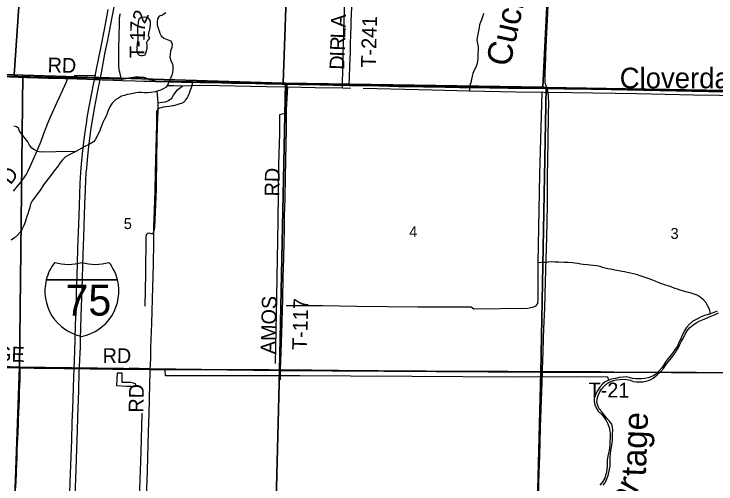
# Model space of a CAD drawing. Extents: x 1443599 to 1910620, y 1028088 to 1361369.
# Drawn here: x 1657763 to 1671995, y 1211112 to 1220636 of the extents above; entities that cross this region are included whole.
import ezdxf

# ---------------------------------------------------------------- set-up
doc = ezdxf.new("R2010")
doc.units = 0
for name, color, linetype in [('GM_X_County_Road', 7, 'Continuous'), ('GM_X_Interstate_Location', 7, 'Continuous'), ('GM_X_Interstate_Route', 7, 'Continuous'), ('GM_X_Interstate_Shield', 7, 'Continuous'), ('GM_X_Major_River', 7, 'Continuous'), ('GM_X_Major_River_Text', 7, 'Continuous'), ('GM_X_Minor_Lake', 7, 'Continuous'), ('GM_X_Minor_River', 7, 'Continuous'), ('GM_X_Minor_River_Text', 7, 'Continuous'), ('GM_X_Section', 7, 'Continuous'), ('GM_X_Section_Text', 7, 'Continuous'), ('GM_X_Township', 7, 'Continuous'), ('GM_X_Township_Road', 7, 'Continuous'), ('GM_X_Township_Road_Text', 7, 'Continuous'), ('GM_X_Unincorporated_Text', 7, 'Continuous')]:
    doc.layers.add(name, color=color, linetype=linetype)

msp = doc.modelspace()

# ---------------------------------------------------------------- linework, layer by layer
at = {"layer": 'GM_X_County_Road'}
for points in [[(1668570, 1219128), (1668552, 1219187), (1668542, 1219216), (1668535, 1219246), (1668530, 1219278), (1668530, 1219294), (1668529, 1219327), (1668531, 1219409), (1668541, 1219622), (1668545, 1219721), (1668549, 1219819), (1668569, 1220262), (1668574, 1220376), (1668588, 1220655), (1668603, 1221016), (1668610, 1221230), (1668626, 1221590), (1668635, 1221754), (1668637, 1221792)], [(1668476, 1213394), (1668478, 1213437), (1668490, 1213781), (1668500, 1214060), (1668507, 1214257), (1668525, 1214683), (1668540, 1215208), (1668547, 1215437), (1668555, 1215683), (1668567, 1216110), (1668574, 1216438), (1668578, 1216766), (1668582, 1217390), (1668585, 1217636), (1668599, 1218571), (1668604, 1218866), (1668603, 1218932), (1668600, 1218980), (1668591, 1219041), (1668577, 1219107), (1668570, 1219128)], [(1668309, 1208097), (1668308, 1208172), (1668312, 1208303), (1668320, 1208549), (1668326, 1208762), (1668336, 1209008), (1668344, 1209287), (1668363, 1209845), (1668392, 1210697), (1668401, 1210927), (1668405, 1211107), (1668412, 1211337), (1668423, 1211682), (1668440, 1212256), (1668469, 1213174), (1668476, 1213394)]]:
    msp.add_lwpolyline(points, dxfattribs=at)
at = {"layer": 'GM_X_Interstate_Route'}
for points in [[(1659004, 1210858), (1659022, 1211400), (1659036, 1211826), (1659047, 1212187), (1659057, 1212466), (1659075, 1213007), (1659087, 1213401), (1659089, 1213450), (1659091, 1213483), (1659100, 1213630), (1659107, 1213761), (1659111, 1213876), (1659114, 1214056), (1659117, 1214270), (1659124, 1214516), (1659143, 1215057), (1659166, 1215762), (1659179, 1216123), (1659201, 1216779), (1659210, 1217075), (1659219, 1217272), (1659228, 1217419), (1659236, 1217511), (1659251, 1217681), (1659273, 1217893), (1659301, 1218121), (1659335, 1218365), (1659366, 1218560), (1659400, 1218754), (1659461, 1219076), (1659508, 1219306), (1659535, 1219446), (1659614, 1219866), (1659662, 1220107), (1659727, 1220433), (1659756, 1220574), (1659833, 1220977)], [(1658897, 1210943), (1658910, 1211321), (1658932, 1212009), (1658942, 1212354), (1658953, 1212633), (1658975, 1213273), (1658981, 1213452), (1658993, 1213798), (1659009, 1214323), (1659021, 1214651), (1659032, 1214995), (1659044, 1215340), (1659051, 1215578), (1659060, 1215881), (1659073, 1216209), (1659083, 1216554), (1659097, 1216980), (1659107, 1217210), (1659120, 1217422), (1659134, 1217602), (1659160, 1217864), (1659181, 1218043), (1659213, 1218287), (1659237, 1218460), (1659240, 1218482), (1659262, 1218611), (1659323, 1218934), (1659397, 1219310), (1659430, 1219482), (1659534, 1220013), (1659628, 1220496), (1659674, 1220729)]]:
    msp.add_lwpolyline(points, dxfattribs=at)
at = {"layer": 'GM_X_Interstate_Shield'}
for p, q in [((1658417, 1215250), (1659860, 1215250)), ((1659860, 1215250), (1658417, 1215250)), ((1659860, 1215250), (1658417, 1215250))]:
    msp.add_line(p, q, dxfattribs=at)
for centre, start, end in [((1659326, 1215021), 141.669, 165.8066), ((1658865, 1216499), 253.0091, 286.9909), ((1659413, 1216499), 253.0091, 286.9909), ((1658951, 1215021), 14.1934, 38.331), ((1659326, 1215021), 165.8066, 258.463), ((1658951, 1215021), 281.537, 14.1934)]:
    msp.add_arc(centre, 938, start, end, dxfattribs=at)
at = {"layer": 'GM_X_Major_River'}
for points in [[(1660838, 1220661), (1660773, 1220610), (1660704, 1220593), (1660669, 1220538), (1660664, 1220482), (1660667, 1220420), (1660686, 1220351), (1660703, 1220297), (1660718, 1220246), (1660745, 1220196), (1660799, 1220145), (1660868, 1220117), (1660940, 1220090), (1660967, 1220027), (1660960, 1219957), (1660938, 1219885), (1660927, 1219819), (1660924, 1219763), (1660943, 1219697), (1660974, 1219622), (1660983, 1219570), (1660984, 1219505), (1660979, 1219453), (1660960, 1219399), (1660941, 1219348), (1660918, 1219292), (1660886, 1219220), (1660851, 1219153), (1660800, 1219124), (1660733, 1219091), (1660683, 1219078), (1660623, 1219061), (1660536, 1219046), (1660470, 1219037), (1660406, 1219040), (1660347, 1219045), (1660285, 1219044), (1660233, 1219037), (1660176, 1219024), (1660112, 1219012), (1660060, 1219002), (1660001, 1218987), (1659943, 1218968), (1659880, 1218933), (1659829, 1218904), (1659752, 1218831), (1659706, 1218754), (1659675, 1218678), (1659651, 1218619), (1659628, 1218567), (1659591, 1218493), (1659566, 1218436), (1659545, 1218384), (1659518, 1218316), (1659494, 1218256), (1659405, 1218084)], [(1659405, 1218084), (1659372, 1218044), (1659272, 1217985), (1659212, 1217959), (1659141, 1217919), (1659079, 1217885), (1659013, 1217849), (1658951, 1217819), (1658883, 1217784), (1658810, 1217742), (1658748, 1217682), (1658694, 1217612), (1658661, 1217562), (1658607, 1217495), (1658557, 1217431), (1658509, 1217363), (1658458, 1217299), (1658362, 1217171), (1658322, 1217107), (1658279, 1217047), (1658227, 1216981), (1658183, 1216917), (1658134, 1216849), (1658096, 1216779), (1658082, 1216715), (1658062, 1216653), (1658041, 1216584), (1658023, 1216530), (1658005, 1216468), (1657987, 1216418), (1657959, 1216348), (1657926, 1216284), (1657886, 1216216), (1657836, 1216154), (1657776, 1216098), (1657707, 1216050)], [(1672021, 1214612), (1671953, 1214584), (1671884, 1214563), (1671815, 1214540), (1671765, 1214527), (1671696, 1214498), (1671646, 1214469), (1671583, 1214441), (1671528, 1214411), (1671459, 1214350), (1671395, 1214285), (1671356, 1214217), (1671315, 1214144), (1671296, 1214092), (1671275, 1214038), (1671245, 1213977), (1671214, 1213907), (1671161, 1213834), (1671130, 1213782), (1671088, 1213731), (1671027, 1213656), (1670980, 1213594), (1670938, 1213527), (1670895, 1213463), (1670792, 1213347), (1670723, 1213304), (1670663, 1213275)], [(1670723, 1213256), (1670806, 1213321), (1670870, 1213386), (1670929, 1213453), (1670980, 1213524), (1671032, 1213593), (1671095, 1213668), (1671139, 1213732), (1671229, 1213867), (1671253, 1213923), (1671294, 1214004), (1671337, 1214073), (1671371, 1214145), (1671412, 1214214), (1671461, 1214274), (1671525, 1214329), (1671592, 1214376), (1671655, 1214410), (1671725, 1214439), (1671770, 1214461), (1671841, 1214491), (1671911, 1214518), (1671982, 1214547), (1672049, 1214580)], [(1670663, 1213275), (1670621, 1213263), (1670546, 1213247), (1670484, 1213244), (1670417, 1213241), (1670365, 1213244), (1670305, 1213251), (1670237, 1213267), (1670175, 1213280), (1670111, 1213279), (1670033, 1213266), (1669958, 1213250), (1669878, 1213233), (1669823, 1213218), (1669752, 1213179), (1669698, 1213131), (1669642, 1213075), (1669592, 1212998), (1669566, 1212949), (1669527, 1212846), (1669524, 1212782), (1669539, 1212712), (1669570, 1212643), (1669609, 1212590), (1669676, 1212525), (1669731, 1212462), (1669772, 1212397), (1669801, 1212330), (1669830, 1212259), (1669843, 1212195), (1669847, 1212127), (1669850, 1212054), (1669845, 1211980), (1669843, 1211906), (1669838, 1211850), (1669829, 1211792), (1669816, 1211734), (1669805, 1211678), (1669792, 1211604), (1669786, 1211520), (1669787, 1211468), (1669784, 1211416), (1669773, 1211344), (1669758, 1211288), (1669739, 1211232), (1669704, 1211163), (1669640, 1211087)], [(1669710, 1211090), (1669753, 1211150), (1669785, 1211213), (1669808, 1211283), (1669823, 1211343), (1669838, 1211409), (1669848, 1211475), (1669849, 1211539), (1669848, 1211607), (1669851, 1211657), (1669856, 1211721), (1669865, 1211789), (1669877, 1211867), (1669894, 1211941), (1669897, 1212005), (1669896, 1212081), (1669896, 1212130), (1669903, 1212196), (1669897, 1212260), (1669883, 1212324), (1669832, 1212392), (1669775, 1212453), (1669720, 1212520), (1669679, 1212571), (1669630, 1212636), (1669597, 1212699), (1669582, 1212767), (1669585, 1212831), (1669607, 1212907), (1669642, 1212979), (1669677, 1213030), (1669729, 1213093), (1669798, 1213154), (1669865, 1213191), (1669919, 1213210), (1669980, 1213221), (1670050, 1213232), (1670151, 1213235), (1670220, 1213221), (1670254, 1213212), (1670320, 1213191), (1670386, 1213180), (1670440, 1213179), (1670514, 1213181), (1670583, 1213196), (1670627, 1213211), (1670672, 1213231), (1670723, 1213256)]]:
    msp.add_lwpolyline(points, dxfattribs=at)
at = {"layer": 'GM_X_Minor_Lake'}
for p, q in [((1660268, 1220333), (1660272, 1220118)), ((1659954, 1213354), (1659852, 1213360))]:
    msp.add_line(p, q, dxfattribs=at)
for points in [[(1660272, 1220118), (1660257, 1220032), (1660256, 1219960), (1660254, 1219891), (1660269, 1219837), (1660301, 1219800), (1660335, 1219796), (1660365, 1219795), (1660423, 1219808), (1660451, 1219880), (1660460, 1219944), (1660463, 1219998), (1660458, 1220048), (1660464, 1220086), (1660487, 1220114), (1660514, 1220148), (1660493, 1220194), (1660499, 1220238), (1660523, 1220354), (1660531, 1220432), (1660528, 1220488), (1660503, 1220531), (1660463, 1220566), (1660399, 1220575), (1660327, 1220562), (1660294, 1220533), (1660279, 1220471), (1660274, 1220413), (1660268, 1220333)], [(1659852, 1213360), (1659841, 1213104), (1660047, 1213092), (1660138, 1213092), (1660176, 1213088), (1660206, 1213087), (1660234, 1213097), (1660231, 1213135), (1660183, 1213152), (1660131, 1213165), (1660095, 1213167), (1660043, 1213166), (1659956, 1213166), (1659954, 1213354)]]:
    msp.add_lwpolyline(points, dxfattribs=at)
at = {"layer": 'GM_X_Minor_River'}
for points in [[(1664420, 1219141), (1664430, 1219588), (1664467, 1220703), (1664502, 1221797)], [(1667283, 1220648), (1667261, 1220578), (1667240, 1220521), (1667221, 1220469), (1667204, 1220415), (1667191, 1220363), (1667178, 1220293), (1667165, 1220219), (1667152, 1220157), (1667149, 1220107), (1667161, 1220041), (1667174, 1219970), (1667175, 1219912), (1667166, 1219840), (1667169, 1219786), (1667170, 1219734), (1667163, 1219682), (1667144, 1219616), (1667125, 1219558), (1667095, 1219498), (1667066, 1219433), (1667053, 1219379), (1667038, 1219313), (1667027, 1219243), (1667000, 1219173), (1666996, 1219076)], [(1659424, 1219391), (1658982, 1219384)], [(1660681, 1218837), (1660771, 1218851), (1660832, 1218858), (1660896, 1218883), (1660963, 1218934), (1660997, 1218990), (1661031, 1219037), (1661087, 1219104), (1661136, 1219150), (1661177, 1219183)], [(1660870, 1219189), (1661006, 1219184), (1661177, 1219183), (1661532, 1219193), (1661917, 1219190), (1662884, 1219170), (1663307, 1219159), (1663869, 1219145), (1664420, 1219141), (1664587, 1219132)], [(1663307, 1219159), (1663281, 1218698), (1663272, 1218640), (1663239, 1218615), (1663191, 1218609), (1663146, 1218596), (1663146, 1218570), (1663146, 1218223), (1663124, 1217586), (1663110, 1216437), (1663086, 1214905), (1663055, 1213550)], [(1664842, 1219131), (1666248, 1219098), (1666996, 1219076), (1667940, 1219062), (1669064, 1219046), (1670392, 1219026), (1671541, 1219001), (1673126, 1218979), (1673804, 1218965), (1674957, 1218930), (1676782, 1218885), (1677987, 1218855), (1678918, 1218835), (1679686, 1218817), (1679915, 1218821), (1679981, 1218817), (1680013, 1218811), (1680035, 1218802), (1680071, 1218790), (1680088, 1218782), (1680162, 1218770), (1680189, 1218755), (1680204, 1218737), (1680229, 1218696)], [(1660657, 1219070), (1660672, 1218917), (1660681, 1218837), (1660678, 1218674), (1660662, 1218380), (1660651, 1217762), (1660643, 1217089), (1660609, 1216307), (1660600, 1216243), (1660577, 1216183), (1660545, 1216182), (1660503, 1216197), (1660467, 1216191), (1660446, 1216169), (1660437, 1216127), (1660432, 1215373), (1660416, 1214716)], [(1668462, 1219054), (1668418, 1217385), (1668381, 1215596), (1668384, 1214858), (1668376, 1214766), (1668333, 1214713), (1668277, 1214686), (1668176, 1214671), (1667086, 1214653), (1667031, 1214692), (1665951, 1214695), (1664714, 1214709), (1664012, 1214720), (1663281, 1214719)], [(1659013, 1217849), (1658614, 1217840), (1658304, 1217837), (1658240, 1217852), (1658176, 1217884), (1658124, 1217918), (1658080, 1217978), (1658042, 1218045), (1657876, 1218264), (1657854, 1218322), (1657816, 1218350), (1657758, 1218364)], [(1671884, 1214563), (1671862, 1214657), (1671821, 1214728), (1671794, 1214781), (1671741, 1214842), (1671673, 1214897), (1671612, 1214935), (1671550, 1214960), (1671492, 1214977), (1671414, 1214998), (1671336, 1215016), (1671269, 1215039), (1671217, 1215058), (1671163, 1215075), (1671087, 1215107), (1671023, 1215128), (1670970, 1215143), (1670900, 1215168), (1670824, 1215195), (1670764, 1215221), (1670693, 1215246), (1670641, 1215267), (1670583, 1215286), (1670519, 1215307), (1670459, 1215328), (1670386, 1215354), (1670324, 1215367), (1670260, 1215384), (1670194, 1215397), (1670138, 1215410), (1670084, 1215421), (1670028, 1215432), (1669948, 1215448), (1669858, 1215466), (1669806, 1215474), (1669752, 1215487), (1669698, 1215502), (1669646, 1215517), (1669580, 1215533), (1669506, 1215540), (1669442, 1215545), (1669388, 1215552), (1669306, 1215562), (1669254, 1215569), (1669186, 1215580), (1669136, 1215587), (1669086, 1215592), (1669001, 1215599), (1668919, 1215603), (1668801, 1215605), (1668733, 1215608), (1668663, 1215615), (1668596, 1215608), (1668542, 1215603), (1668460, 1215603), (1668381, 1215596)], [(1669823, 1213218), (1669805, 1213276), (1669173, 1213280), (1668000, 1213277), (1666861, 1213282), (1665834, 1213288), (1664588, 1213293), (1663567, 1213300), (1662885, 1213300), (1661889, 1213306), (1660835, 1213301), (1660826, 1213428), (1660509, 1213444), (1660100, 1213457)], [(1660232, 1208087), (1660232, 1208213), (1660242, 1208400), (1660260, 1209137), (1660290, 1210079), (1660309, 1210818), (1660343, 1211760), (1660364, 1212544)]]:
    msp.add_lwpolyline(points, dxfattribs=at)
at = {"layer": 'GM_X_Section'}
for points in [[(1652516, 1224828), (1658122, 1224661), (1657765, 1219401), (1652475, 1219581)], [(1658122, 1224661), (1663408, 1224572), (1663222, 1219236), (1657943, 1219395), (1657765, 1219401)], [(1663408, 1224572), (1668747, 1224447), (1668485, 1219152), (1663270, 1219233), (1663222, 1219236)], [(1674092, 1224359), (1673808, 1219056), (1668555, 1219147), (1668485, 1219152), (1668747, 1224447)], [(1652475, 1219581), (1657765, 1219401), (1657943, 1219395), (1657875, 1213479), (1652349, 1213674), (1652351, 1213940)], [(1657943, 1219395), (1663222, 1219236), (1663270, 1219233), (1663148, 1213408), (1657875, 1213479)], [(1668485, 1219152), (1668555, 1219147), (1668445, 1213380), (1663148, 1213408), (1663270, 1219233)], [(1668555, 1219147), (1673808, 1219056), (1673892, 1219051), (1673741, 1213362), (1668445, 1213380)], [(1652349, 1213674), (1657875, 1213479), (1657686, 1208189), (1652280, 1208398), (1652277, 1208611)], [(1657875, 1213479), (1663148, 1213408), (1663012, 1208124), (1657686, 1208189)], [(1668445, 1213380), (1668306, 1208094), (1663012, 1208124), (1663148, 1213408)], [(1673741, 1213362), (1673597, 1208030), (1668306, 1208094), (1668445, 1213380)]]:
    msp.add_lwpolyline(points, close=True, dxfattribs=at)
at = {"layer": 'GM_X_Township'}
for points in [[(1652299, 1208613), (1652365, 1213513), (1652367, 1213913), (1652370, 1214308), (1652390, 1216842), (1652463, 1219561), (1656589, 1219402), (1658837, 1219343), (1659402, 1219335), (1659951, 1219317), (1660040, 1219328), (1660129, 1219344), (1660227, 1219355), (1660302, 1219359), (1660400, 1219347), (1660510, 1219312), (1660641, 1219274), (1661382, 1219261), (1663295, 1219213), (1664558, 1219194), (1668556, 1219132), (1673810, 1219028)], [(1673810, 1219028), (1668556, 1219132), (1664558, 1219194), (1663295, 1219213), (1661382, 1219261), (1660641, 1219274), (1660510, 1219312), (1660400, 1219347), (1660302, 1219359), (1660227, 1219355), (1660129, 1219344), (1660040, 1219328), (1659951, 1219317), (1659402, 1219335), (1658837, 1219343), (1656589, 1219402)]]:
    msp.add_lwpolyline(points, dxfattribs=at)
at = {"layer": 'GM_X_Township_Road'}
for points in [[(1664601, 1220488), (1664606, 1220631), (1664614, 1220775), (1664621, 1220933), (1664634, 1221211), (1664640, 1221388), (1664651, 1221641), (1664658, 1221795), (1664660, 1221857), (1664661, 1221891)], [(1659951, 1219290), (1659944, 1219318), (1659907, 1219457), (1659902, 1219477), (1659898, 1219496), (1659894, 1219520), (1659892, 1219538), (1659890, 1219558), (1659888, 1219581), (1659886, 1219630), (1659887, 1219745), (1659889, 1219876), (1659897, 1220263), (1659900, 1220381), (1659900, 1220500), (1659902, 1220523), (1659903, 1220545), (1659905, 1220565), (1659907, 1220585), (1659910, 1220604), (1659914, 1220623), (1659919, 1220645)], [(1664558, 1219189), (1664558, 1219204), (1664559, 1219224), (1664562, 1219326), (1664572, 1219598), (1664576, 1219713), (1664582, 1219867), (1664585, 1219939), (1664588, 1220103), (1664589, 1220146), (1664589, 1220159), (1664590, 1220205), (1664593, 1220264), (1664596, 1220352), (1664601, 1220488)], [(1656645, 1219400), (1656663, 1219399), (1656991, 1219389), (1657237, 1219381), (1657368, 1219375), (1657466, 1219371), (1657598, 1219367), (1657680, 1219364), (1658024, 1219351), (1658451, 1219339), (1658506, 1219338)], [(1658506, 1219338), (1658615, 1219335), (1658795, 1219330), (1658849, 1219328)], [(1658639, 1218850), (1658685, 1218950), (1658788, 1219174), (1658821, 1219249), (1658831, 1219280), (1658849, 1219328)], [(1658849, 1219328), (1659041, 1219322), (1659238, 1219315), (1659397, 1219310), (1659508, 1219306), (1659549, 1219305), (1659583, 1219304), (1659779, 1219296), (1659951, 1219290)], [(1659951, 1219290), (1660222, 1219281), (1660386, 1219275), (1660534, 1219272), (1660632, 1219269)], [(1660526, 1213431), (1660526, 1213432), (1660531, 1213530), (1660535, 1213678), (1660539, 1213874), (1660555, 1214366), (1660578, 1215104), (1660585, 1215317), (1660592, 1215563), (1660601, 1216006), (1660600, 1216153), (1660601, 1216334), (1660611, 1216662), (1660623, 1217055), (1660632, 1217416), (1660639, 1217678), (1660658, 1218399), (1660659, 1218629), (1660661, 1218662), (1660664, 1218678), (1660669, 1218693), (1660678, 1218707), (1660690, 1218719), (1660704, 1218728), (1660718, 1218734), (1660750, 1218744), (1660797, 1218754), (1660847, 1218762), (1660911, 1218771), (1660946, 1218775), (1660976, 1218780), (1660996, 1218783), (1661024, 1218789), (1661072, 1218801), (1661135, 1218820), (1661165, 1218832), (1661195, 1218846), (1661209, 1218855), (1661222, 1218865), (1661232, 1218876), (1661243, 1218889), (1661271, 1218930), (1661295, 1218973), (1661309, 1219002), (1661321, 1219033), (1661336, 1219076), (1661359, 1219147), (1661372, 1219189), (1661376, 1219200), (1661377, 1219209), (1661379, 1219218), (1661380, 1219225), (1661382, 1219253)], [(1660632, 1219269), (1660928, 1219263), (1661157, 1219255), (1661321, 1219254), (1661382, 1219253)], [(1661382, 1219253), (1661535, 1219251), (1661797, 1219246), (1662159, 1219238), (1662437, 1219232), (1662667, 1219228), (1662848, 1219223), (1663012, 1219220), (1663192, 1219215), (1663302, 1219213)], [(1663167, 1213428), (1663171, 1213595), (1663184, 1213972), (1663198, 1214382), (1663204, 1214644), (1663210, 1214841), (1663222, 1215300), (1663228, 1215481), (1663233, 1215710), (1663241, 1216005), (1663245, 1216251), (1663250, 1216547), (1663259, 1216891), (1663267, 1217334), (1663279, 1218006), (1663286, 1218285), (1663290, 1218466), (1663290, 1218580), (1663286, 1218810), (1663290, 1218941), (1663297, 1219122), (1663301, 1219188), (1663302, 1219213)], [(1663302, 1219213), (1663389, 1219212), (1663537, 1219208), (1663767, 1219205), (1663964, 1219200), (1664243, 1219196), (1664456, 1219191), (1664558, 1219189)], [(1664558, 1219189), (1664784, 1219187), (1665162, 1219179), (1665556, 1219170), (1666065, 1219162), (1666508, 1219153), (1666803, 1219149), (1667050, 1219146), (1667411, 1219140), (1667788, 1219136), (1668100, 1219131), (1668570, 1219128)], [(1668570, 1219128), (1668921, 1219123), (1669150, 1219119), (1669462, 1219115), (1669889, 1219109), (1670168, 1219107), (1670628, 1219101), (1670858, 1219096), (1671071, 1219094), (1671334, 1219089), (1671760, 1219084), (1672335, 1219072), (1672565, 1219071), (1673336, 1219059), (1673550, 1219056), (1673664, 1219055), (1673802, 1219055)], [(1657752, 1217047), (1657925, 1217265), (1657974, 1217331), (1658001, 1217372), (1658027, 1217414), (1658049, 1217458), (1658090, 1217547), (1658170, 1217727), (1658230, 1217862), (1658276, 1217967), (1658312, 1218059), (1658366, 1218213), (1658412, 1218336), (1658449, 1218427), (1658508, 1218563), (1658639, 1218850)], [(1657599, 1213475), (1657845, 1213469), (1657890, 1213468)], [(1657801, 1211030), (1657809, 1211193), (1657813, 1211288), (1657815, 1211357), (1657820, 1211518), (1657825, 1211636), (1657826, 1211685), (1657830, 1211800), (1657836, 1211941), (1657845, 1212144), (1657851, 1212328), (1657854, 1212403), (1657860, 1212567), (1657864, 1212679), (1657871, 1212849), (1657872, 1212875), (1657874, 1212928), (1657877, 1213023), (1657878, 1213062), (1657885, 1213269), (1657888, 1213374), (1657889, 1213416), (1657890, 1213451), (1657890, 1213468)], [(1657890, 1213468), (1658038, 1213464)], [(1658038, 1213464), (1658174, 1213461), (1658338, 1213459), (1658617, 1213456), (1658781, 1213455), (1658981, 1213452), (1659089, 1213450), (1659306, 1213447), (1659552, 1213443), (1659765, 1213441), (1659962, 1213437), (1660045, 1213437)], [(1660045, 1213437), (1660126, 1213436), (1660274, 1213435), (1660526, 1213431)], [(1660360, 1208186), (1660360, 1208196), (1660360, 1208234), (1660360, 1208297), (1660365, 1208481), (1660378, 1208793), (1660394, 1209268), (1660411, 1209694), (1660421, 1210006), (1660430, 1210235), (1660435, 1210399), (1660449, 1210809), (1660468, 1211383), (1660490, 1212169), (1660501, 1212530), (1660508, 1212809), (1660515, 1213170), (1660521, 1213350), (1660526, 1213431)], [(1660526, 1213431), (1660536, 1213431), (1661111, 1213432), (1661357, 1213433), (1661702, 1213433), (1661997, 1213432), (1662309, 1213432), (1662670, 1213430), (1662933, 1213429), (1663167, 1213428)], [(1663166, 1213225), (1663167, 1213338), (1663167, 1213418), (1663167, 1213428)], [(1663167, 1213428), (1663245, 1213427), (1663803, 1213422), (1664147, 1213420), (1664344, 1213418), (1665149, 1213410), (1665543, 1213406), (1665822, 1213403), (1666117, 1213402), (1666494, 1213399), (1666675, 1213398), (1666839, 1213398), (1667019, 1213396), (1667282, 1213396), (1667577, 1213396), (1667774, 1213396), (1667939, 1213394), (1668431, 1213394), (1668476, 1213394)], [(1668476, 1213394), (1668529, 1213394), (1668759, 1213391), (1669137, 1213391), (1669662, 1213389), (1669925, 1213385), (1670171, 1213379), (1670532, 1213377), (1670679, 1213378), (1670844, 1213380), (1671041, 1213378), (1671270, 1213379), (1671599, 1213376), (1671779, 1213374), (1672370, 1213372), (1672600, 1213371), (1672830, 1213370), (1673174, 1213369), (1673388, 1213370), (1673716, 1213368), (1673782, 1213368)]]:
    msp.add_lwpolyline(points, dxfattribs=at)

# ---------------------------------------------------------------- texts
at = {"layer": 'GM_X_Interstate_Location'}
for s in ['.', '-', ',']:
    msp.add_text(s, height=1, dxfattribs=at).set_placement((1659139, 1214851))
msp.add_text('75', height=1, rotation=0, dxfattribs=at).set_placement((1658934, 1214644))
at = {"layer": 'GM_X_Interstate_Shield'}
msp.add_text('75', height=625, dxfattribs=at).set_placement((1658805, 1214524))
at = {"layer": 'GM_X_Major_River_Text'}
for s, height, rotation, p in [('tage', 500.2, 87.896, (1670572, 1211261)), ('or', 500.3, 60.895, (1670195, 1210574))]:
    msp.add_text(s, height=height, rotation=rotation, dxfattribs=at).set_placement(p)
at = {"layer": 'GM_X_Minor_River_Text'}
msp.add_text('Cuckle', height=500.3, rotation=77.4227, dxfattribs=at).set_placement((1667815, 1219549))
at = {"layer": 'GM_X_Section_Text'}
for s, p in [('5', (1659988, 1216278)), ('4', (1665776, 1216115)), ('3', (1671074, 1216078))]:
    msp.add_text(s, height=221, rotation=0, dxfattribs=at).set_placement(p)
at = {"layer": 'GM_X_Township_Road_Text'}
for s, rotation, p in [('2', 65.0293, (1660414, 1220422)), ('A', 88.0634, (1664486, 1220360)), ('T-241', 88.367, (1665096, 1219546)), ('7', 88.7607, (1660417, 1220269)), ('1', 88.7521, (1660413, 1220084)), ('L', 88.0583, (1664478, 1220136)), ('R', 88.0599, (1664470, 1219890)), ('T', 88.7485, (1660405, 1219736)), ('-', 88.7431, (1660410, 1219961)), ('I', 88.0641, (1664465, 1219767)), ('RD', 358.5255, (1658441, 1219456)), ('D', 88.0581, (1664457, 1219503)), ('D', 51.487, (1657691, 1217162)), ('RD', 89.0128, (1663142, 1216937)), ('AMOS', 88.5796, (1663062, 1213739)), ('T-117', 88.3199, (1663701, 1213823)), ('PORTAGE', 357.9285, (1656014, 1213656)), ('RD', 359.5061, (1659558, 1213564)), ('T-21', 359.6465, (1669412, 1212868)), ('RD', 89.0128, (1660387, 1212555))]:
    msp.add_text(s, height=300, rotation=rotation, dxfattribs=at).set_placement(p)
at = {"layer": 'GM_X_Unincorporated_Text'}
msp.add_text('Cloverdale', height=417, rotation=0, dxfattribs=at).set_placement((1670044, 1219131))

doc.saveas('drawing.dxf')
